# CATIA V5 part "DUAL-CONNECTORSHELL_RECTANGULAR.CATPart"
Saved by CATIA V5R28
Part number: DUAL-CONNECTOR_RECTANGULAR
Revision: ---
Publications: "Logical Termination.1", "Logical Pin.1", "CAVA", "Face_generated(CAV1)", "Axis_generated(CAV1)", "Face_generated(CAV1).1", "CAVB", "Face_generated(CAV2)", "Axis_generated(CAV2)", "Face_generated(CAV2).1", "CaCP", "Face_generated(CaCP1)", "Axis_generated(CaCP1)", "Face_generated(CaCP1).1", "BaCP", "BCP", "BCPRPoint_generated(BCP)", "BCPPlane_generated(BCP)", "Axis_generated(CAVA)", "Axis_generated(CAVB)", "Face_generated(BaCP)", "Axis_generated(BaCP)", "Face_generated(BaCP).1", "SCP", "Face_generated(SCP)", "Axis_generated(SCP)", "Face_generated(SCP).1"
Bounding box of the stored display mesh (mm): x 0 to 32.258, y -45.847 to 45.847, z -9.83 to 9.83
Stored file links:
  C:\Users\ajc8720\Documents\BOEING_WORK\0001-2CES\004-AP242\Boeing-Generic_Harness_R3\DUAL-CONNECTORSHELL_RECTANGULAR.CATPart
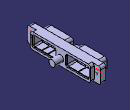
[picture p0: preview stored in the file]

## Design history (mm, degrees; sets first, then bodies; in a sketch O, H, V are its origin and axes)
Parameters
  PartNumber = "BACC65AA2AF"
  OverallLength = 21.59 mm
  OverallWidth = 91.694 mm
  OverallHeight = 19.6596 mm
  ShellBodyLength = 21.59 mm
  ShellFlangeThickness = 6.5024 mm
  ShellFlangeCornerRadius = 2.9972 mm
  ShellFlangeLocation = 10.668 mm
  ShellEngagingEndWidth = 30.9626 mm
  ShellEngagingEndHeight = 13.9446 mm
  ShellEngagingEndInsertCavityWidth = 27.051 mm
  ShellEngagingEndInsertCavityHeight = 11.2522 mm
  ShellEngagingEndOuterRadius = 3.1242 mm
  ShellEngagingEndInnerRadius = 1.7272 mm
  ShellRearInsertCavityWidth = 29.7942 mm
  ShellRearInsertCavityLength = 11.2014 mm
  ShellRearInsertCavityHeight = 14.1986 mm
  ShellInsertCavityRadius = 2.286 mm
  ShellInsertKeywayRadius = 3.5052 mm
  ShellInsertKeywayLength = 12.6492 mm
  ShellInsertKeywayDepth = 13.1826 mm
  ShellInsertKeywaySpacing = 7.62 mm
  BackInsertCavitySecondTransitionWidth = 27.1272 mm
  ShellCouplingPostVerticalLocation = 1.4986 mm
  CouplingPostOD = 7.9502 mm
  CouplingPostProtrusion = 10.668 mm
  ShellEngagingEndSpacing = 11.0744 mm
  CouplingPostID = 7.239 mm
  ShellEngagingEndInsertCavityDepth = 7.62 mm
  BackInsertCavitySecondTransitionRadius = 1.4986 mm
  BackInsertCavitySecondTransitionHeight = 12.0904 mm
  ShellRearWidth = 75.4888 mm
  ShellRearRadius = 2.9972 mm
  `Change of the Polarization Keyway` = "http://www.boeing.com/product_standards/tps2?part=\"BACC65AA2AF\"&suop=\"Change+of+the+Polarization+Keyway\""
  `Jackscrew Installation` = "http://www.boeing.com/product_standards/tps2?part=\"BACC65AA2AF\"&suop=\"Jackscrew+Installation\""
  `Jackscrew Removal` = "http://www.boeing.com/product_standards/tps2?part=\"BACC65AA2AF\"&suop=\"Jackscrew+Removal\""
  `Plug and Receptacle Connection` = "http://www.boeing.com/product_standards/tps2?part=\"BACC65AA2AF\"&suop=\"Plug+and+Receptacle+Connection\""
  P_Part_1 = "Loctite222"
  P_Name_1 = "Adhesive"
  P_Qty_1 = "As required"
TTRSSet1
f4a2d38f3ddc11d3a929006094b99c4b_11 "CATTPSSet"
Set1 "EGFOBody"
  Set2 "CaCPOBody1"
    Point1 "CaCPRPoint1": (10.668 {= ShellFlangeLocation}, 0, -1.4986 {= - BackInsertCavitySecondTransitionRadius})
    Plane1 "CaCPCPlane1": type OffsetPt, RefPlane yz-plane, RefPoint Point1
  Set3 "Construction Geometry"
    Plane2: type Offset, RefPlane yz-plane, Offset 21.59 {= ShellBodyLength}
    Sketch1 on Plane2, origin (21.59, 0, 0), H (0, 1, 0), V (0, 0, 1)
      line L1 (45.847, 6.8326) -> (45.847, -6.8326)
      line L2 (42.8498, -9.8298) -> (-42.8498, -9.8298)
      line L3 (-45.847, -6.8326) -> (-45.847, 6.8326)
      line L4 (-42.8498, 9.8298) -> (42.8498, 9.8298)
      point P1 (45.847, 9.8298)
      point P2 (45.847, -9.8298)
      point P3 (-45.847, 9.8298)
      arc A1 centre (42.8498, 6.8326) radius 2.9972 from (42.8498, 9.8298) to (45.847, 6.8326) cw
      arc A2 centre (42.8498, -6.8326) radius 2.9972 from (45.847, -6.8326) to (42.8498, -9.8298) cw
      arc A3 centre (-42.8498, -6.8326) radius 2.9972 from (-42.8498, -9.8298) to (-45.847, -6.8326) cw
      arc A4 centre (-42.8498, 6.8326) radius 2.9972 from (-45.847, 6.8326) to (-42.8498, 9.8298) cw
      distance P3 P1 = 91.694 {= OverallWidth}
      distance P1 P2 = 19.6596 {= OverallHeight}
      radius A1 = 2.9972 {= ShellFlangeCornerRadius}
      radius A2 = 2.9972 {= ShellFlangeCornerRadius}
      radius A3 = 2.9972 {= ShellFlangeCornerRadius}
      radius A4 = 2.9972 {= ShellFlangeCornerRadius}
      vertical: L1 V, L3 V
      horizontal: L2 H, L4 H
      equidistance: L1 L3 O, L2 L4 O
      coincidence: L4 P1, L1 P1, L1 P2, L2 P2, L3 P3, L4 P3
      tangency: A1 L4, A1 L1, A2 L1, A2 L2, A3 L2, A3 L3, A4 L3, A4 L4
    Plane3 "Ref Plane": type Offset, RefPlane yz-plane, Offset 0
    Plane4: type Offset, RefPlane Plane3, Offset 17.1704 {= ShellFlangeLocation + ShellFlangeThickness}
    Plane5: type Offset, RefPlane Plane3, Offset 10.668 {= ShellFlangeLocation}
    Plane6: type Offset, RefPlane Plane3, Offset 21.59 {= OverallLength}
    Plane7 "Keyway": type Offset, RefPlane Plane3, Offset 4.5212 {= (ShellFlangeLocation +ShellFlangeThickness )-ShellInsertKeywayLength}
    Plane8 "KeywayPlane": type Offset, RefPlane end face of Pad2, Offset 7.62 {= ShellEngagingEndInsertCavityDepth}
    Plane9: type Offset, RefPlane face of Pocket2 from Sketch4.L4, Offset 0, reversed
    Plane10: type Offset, RefPlane end face of Pocket1, Offset 0, reversed
  Set4 "CAVOBody1"
    Plane11 "CAVCPlane": type Offset, RefPlane Plane2, Offset 11.2014 {= ShellRearInsertCavityLength}, reversed
    Point2 "CAVRPoint1": type OnPlane, Support Plane11, H 21.0185 {= (ShellEngagingEndSpacing /2) + (ShellEngagingEndWidth /2)}, V 0, Direction (0, 1, 0)
  Set5 "CAVOBody2"
    Point3 "CAVRPoint2": type OnPlane, Support Plane11, H -21.0185 {= -((ShellEngagingEndSpacing /2) + (ShellEngagingEndWidth /2))}, V 0, Direction (0, 1, 0)
  Set6 "BaCPOBody"
    Point4 "BaCPRPoint": (21.59, 0, 0)
    Plane12 "BaCPPlane": type OffsetPt, RefPlane yz-plane, RefPoint Point4
    Line1 "BaCPCLine": type PtDir, RefPoint Point4, Direction zx-plane, Start 0, End -20
  Set7 "BCPOBody"
    Point5 "BCPRPoint": type OnPlane, Support Plane12, H 0, V 0, Direction (0, 1, 0)
    Plane13 "BCPPlane": type OffsetPt, RefPlane yz-plane, RefPoint Point5
  Set8 "SCPOBody"
    Point6 "SCPRPoint": (10.541, 0, 0)
    Plane14 "SCPCPlane": type OffsetPt, RefPlane end face of Pad1, RefPoint Point6
Body1 (main body)
  Pad1: profile Sketch1, direction (-1, 0, 0), up to Plane5
  Sketch2 on start face of Pad1, origin (21.59, 0, 0), H (0, 1, 0), V (0, 0, 1)
    line L1 (45.847, 6.8326) -> (45.847, -6.8326)
    line L2 (42.8498, -9.8298) -> (34.7472, -9.8298)
    line L3 (-45.847, -6.8326) -> (-45.847, 6.8326)
    line L4 (-42.8498, 9.8298) -> (-34.7472, 9.8298)
    point P1 (45.847, 9.8298)
    point P2 (45.847, -9.8298)
    point P3 (-45.847, 9.8298)
    arc A1 centre (42.8498, 6.8326) radius 2.9972 from (42.8498, 9.8298) to (45.847, 6.8326) cw
    arc A2 centre (42.8498, -6.8326) radius 2.9972 from (45.847, -6.8326) to (42.8498, -9.8298) cw
    arc A3 centre (-42.8498, -6.8326) radius 2.9972 from (-42.8498, -9.8298) to (-45.847, -6.8326) cw
    arc A4 centre (-42.8498, 6.8326) radius 2.9972 from (-45.847, 6.8326) to (-42.8498, 9.8298) cw
    line L5 (37.7444, 6.8326) -> (37.7444, -6.8326)
    line L6 (-37.7444, -6.8326) -> (-37.7444, 6.8326)
    point P16 (37.7444, 9.8298)
    point P17 (37.7444, -9.8298)
    point P18 (-37.7444, 9.8298)
    arc A5 centre (34.7472, 6.8326) radius 2.9972 from (34.7472, 9.8298) to (37.7444, 6.8326) cw
    arc A6 centre (34.7472, -6.8326) radius 2.9972 from (37.7444, -6.8326) to (34.7472, -9.8298) cw
    point P22 (34.7472, -9.8298)
    arc A7 centre (-34.7472, -6.8326) radius 2.9972 from (-34.7472, -9.8298) to (-37.7444, -6.8326) cw
    arc A8 centre (-34.7472, 6.8326) radius 2.9972 from (-37.7444, 6.8326) to (-34.7472, 9.8298) cw
    line L7 (-34.7472, -9.8298) -> (-42.8498, -9.8298)
    line L8 (34.7472, 9.8298) -> (42.8498, 9.8298)
    distance P3 P1 = 91.694 {= OverallWidth}
    distance P1 P2 = 19.6596 {= OverallHeight}
    radius A1 = 2.9972 {= ShellFlangeCornerRadius}
    radius A2 = 2.9972 {= ShellFlangeCornerRadius}
    radius A3 = 2.9972 {= ShellFlangeCornerRadius}
    radius A4 = 2.9972 {= ShellFlangeCornerRadius}
    distance P16 P17 = 19.6596 {= OverallHeight}
    radius A5 = 2.9972 {= ShellRearRadius}
    radius A6 = 2.9972 {= ShellRearRadius}
    radius A7 = 2.9972 {= ShellRearRadius}
    radius A8 = 2.9972 {= ShellRearRadius}
    distance L5 L6 = 75.4888 {= ShellRearWidth}
    vertical: L1 V, L3 V, L5 V, L6 V
    horizontal: L2 H, L4 H
    equidistance: L1 L3 O, L2 L4 O, L5 L6 O
    coincidence: L4 P1, L1 P1, L1 P2, L2 P2, L3 P3, L4 P3, L5 P16, L5 P17, L6 P18, L2 L7, P22 L2, P22 A6, P22 L7, L4 L8
    tangency: A1 L4, A1 L1, A2 L1, A2 L2, A3 L2, A3 L3, A4 L3, A4 L4, A5 L5, A6 L5, A7 L6, A8 L6, A8 L4, A7 L7, A6 L2, A5 L8
    symmetry: L5 L6 V
  Pocket1: profile Sketch2, direction (-1, 0, 0), length 4.4196 {= ShellBodyLength -ShellFlangeThickness -ShellFlangeLocation}
  Sketch3 on end face of Pad1, origin (10.668, 0, 0), H (0, -1, 0), V (0, 0, 1)
    point P1 (21.0185, 0)
    line L1 (36.4998, 3.8481) -> (36.4998, -3.8481)
    line L2 (33.3756, -6.9723) -> (8.6614, -6.9723)
    line L3 (5.5372, -3.8481) -> (5.5372, 3.8481)
    line L4 (8.6614, 6.9723) -> (33.3756, 6.9723)
    point P2 (36.4998, 6.9723)
    point P3 (36.4998, -6.9723)
    point P4 (5.5372, 6.9723)
    point P5 (-21.0185, 0)
    line L5 (-5.5372, 3.8481) -> (-5.5372, -3.8481)
    line L6 (-8.6614, -6.9723) -> (-33.3756, -6.9723)
    line L7 (-36.4998, -3.8481) -> (-36.4998, 3.8481)
    line L8 (-33.3756, 6.9723) -> (-8.6614, 6.9723)
    point P6 (-5.5372, 6.9723)
    point P7 (-36.4998, 6.9723)
    arc A1 centre (33.3756, 3.8481) radius 3.1242 from (33.3756, 6.9723) to (36.4998, 3.8481) cw
    arc A2 centre (33.3756, -3.8481) radius 3.1242 from (36.4998, -3.8481) to (33.3756, -6.9723) cw
    arc A3 centre (8.6614, -3.8481) radius 3.1242 from (8.6614, -6.9723) to (5.5372, -3.8481) cw
    arc A4 centre (8.6614, 3.8481) radius 3.1242 from (5.5372, 3.8481) to (8.6614, 6.9723) cw
    arc A5 centre (-8.6614, 3.8481) radius 3.1242 from (-5.5372, 3.8481) to (-8.6614, 6.9723) ccw
    arc A6 centre (-8.6614, -3.8481) radius 3.1242 from (-5.5372, -3.8481) to (-8.6614, -6.9723) cw
    arc A7 centre (-33.3756, -3.8481) radius 3.1242 from (-33.3756, -6.9723) to (-36.4998, -3.8481) cw
    arc A8 centre (-33.3756, 3.8481) radius 3.1242 from (-36.4998, 3.8481) to (-33.3756, 6.9723) cw
    distance P1 V = 21.0185 {= (ShellEngagingEndSpacing/2)+(ShellEngagingEndWidth /2)}
    distance P4 P2 = 30.9626 {= ShellEngagingEndWidth}
    distance P2 P3 = 13.9446 {= ShellEngagingEndHeight}
    radius A1 = 3.1242 {= ShellEngagingEndOuterRadius}
    radius A2 = 3.1242 {= ShellEngagingEndOuterRadius}
    radius A3 = 3.1242 {= ShellEngagingEndOuterRadius}
    radius A4 = 3.1242 {= ShellEngagingEndOuterRadius}
    distance P7 P6 = 30.9626 {= ShellEngagingEndWidth}
    radius A5 = 3.1242 {= ShellEngagingEndOuterRadius}
    radius A6 = 3.1242 {= ShellEngagingEndOuterRadius}
    radius A7 = 3.1242 {= ShellEngagingEndOuterRadius}
    radius A8 = 3.1242 {= ShellEngagingEndOuterRadius}
    coincidence: P1 H, P5 H, L8 L4, L4 P2, L1 P2, L1 P3, L2 P3, L3 P4, L4 P4, L5 P6, L8 P6, L7 P7, L8 P7
    vertical: L1 V, L3 V, L5 V, L7 V
    horizontal: L2 H, L4 H, L6 H, L8 H
    equidistance: L1 L3 P1, L2 L4 P1, L5 L7 P5, L6 L8 P5
    symmetry: P1 P5 V
    tangency: A1 L4, A1 L1, A2 L1, A2 L2, A3 L2, A3 L3, A4 L3, A4 L4, A5 L5, A5 L8, A6 L5, A6 L6, A7 L6, A7 L7, A8 L7, A8 L8
  Pad2: profile Sketch3, direction (-1, 0, 0), length 10.668 {= ShellFlangeLocation}
  Sketch4 on start face of Pad1, origin (21.59, 0, 0), H (0, 1, 0), V (0, 0, 1)
    point P1 (21.0185, 0)
    line L1 (35.9156, 4.8133) -> (35.9156, -4.8133)
    line L2 (33.6296, -7.0993) -> (8.4074, -7.0993)
    line L3 (6.1214, -4.8133) -> (6.1214, 4.8133)
    line L4 (8.4074, 7.0993) -> (33.6296, 7.0993)
    point P2 (35.9156, 7.0993)
    point P3 (35.9156, -7.0993)
    point P4 (6.1214, 7.0993)
    point P5 (-21.0185, 0)
    line L5 (-35.9156, 4.8133) -> (-35.9156, -4.8133)
    line L6 (-33.6296, -7.0993) -> (-8.4074, -7.0993)
    line L7 (-6.1214, -4.8133) -> (-6.1214, 4.8133)
    line L8 (-8.4074, 7.0993) -> (-33.6296, 7.0993)
    point P6 (-35.9156, 7.0993)
    point P7 (-6.1214, 7.0993)
    reference intersected line E2 through (0, 0) direction (0, 1) from zx-plane
    arc A1 centre (33.6296, 4.8133) radius 2.286 from (33.6296, 7.0993) to (35.9156, 4.8133) cw
    arc A2 centre (33.6296, -4.8133) radius 2.286 from (35.9156, -4.8133) to (33.6296, -7.0993) cw
    arc A3 centre (8.4074, -4.8133) radius 2.286 from (8.4074, -7.0993) to (6.1214, -4.8133) cw
    arc A4 centre (8.4074, 4.8133) radius 2.286 from (6.1214, 4.8133) to (8.4074, 7.0993) cw
    arc A5 centre (-8.4074, 4.8133) radius 2.286 from (-6.1214, 4.8133) to (-8.4074, 7.0993) ccw
    arc A6 centre (-8.4074, -4.8133) radius 2.286 from (-6.1214, -4.8133) to (-8.4074, -7.0993) cw
    arc A7 centre (-33.6296, -4.8133) radius 2.286 from (-33.6296, -7.0993) to (-35.9156, -4.8133) cw
    arc A8 centre (-33.6296, 4.8133) radius 2.286 from (-35.9156, 4.8133) to (-33.6296, 7.0993) cw
    distance V P1 = 21.0185 {= (ShellEngagingEndSpacing /2)+(ShellEngagingEndWidth /2)}
    distance P4 P2 = 29.7942 {= ShellRearInsertCavityWidth}
    distance P2 P3 = 14.1986 {= ShellRearInsertCavityHeight}
    radius A1 = 2.286 {= ShellInsertCavityRadius}
    radius A2 = 2.286 {= ShellInsertCavityRadius}
    radius A3 = 2.286 {= ShellInsertCavityRadius}
    radius A4 = 2.286 {= ShellInsertCavityRadius}
    distance P7 P6 = 29.7942 {= ShellRearInsertCavityWidth}
    radius A5 = 2.286 {= ShellInsertCavityRadius}
    radius A6 = 2.286 {= ShellInsertCavityRadius}
    radius A7 = 2.286 {= ShellInsertCavityRadius}
    radius A8 = 2.286 {= ShellInsertCavityRadius}
    coincidence: P1 H, P5 H, L4 L8, L6 L2, L4 P2, L1 P2, L1 P3, L2 P3, L3 P4, L4 P4, L7 P7, L8 P7, L5 P6, L8 P6
    vertical: L1 V, L3 V, L5 V, L7 V
    horizontal: L2 H, L4 H, L6 H, L8 H
    equidistance: L1 L3 P1, L2 L4 P1, L5 L7 P5, L6 L8 P5
    symmetry: P5 P1 E2
    tangency: A1 L4, A1 L1, A2 L1, A2 L2, A3 L2, A3 L3, A4 L3, A4 L4, A5 L7, A5 L8, A6 L7, A6 L6, A7 L6, A7 L5, A8 L5, A8 L8
  Pocket2: profile Sketch4, direction (-1, 0, 0), length 1.3208 {= ShellBodyLength -ShellEngagingEndInsertCavityDepth -ShellInsertKeywayLength}
  Sketch5 on end face of Pocket2, origin (20.2692, 0, 0), H (0, 1, 0), V (0, 0, 1)
    point P1 (21.0185, 0)
    line L1 (34.5821, 4.5466) -> (34.5821, -4.5466)
    line L2 (33.0835, -6.0452) -> (8.9535, -6.0452)
    line L3 (7.4549, -4.5466) -> (7.4549, 4.5466)
    line L4 (8.9535, 6.0452) -> (33.0835, 6.0452)
    point P2 (34.5821, 6.0452)
    point P3 (34.5821, -6.0452)
    point P4 (7.4549, 6.0452)
    point P5 (-21.0185, 0)
    line L5 (-7.4549, 4.5466) -> (-7.4549, -4.5466)
    line L6 (-8.9535, -6.0452) -> (-33.0835, -6.0452)
    line L7 (-34.5821, -4.5466) -> (-34.5821, 4.5466)
    line L8 (-33.0835, 6.0452) -> (-8.9535, 6.0452)
    point P6 (-7.4549, 6.0452)
    point P7 (-34.5821, 6.0452)
    reference intersected line E1 through (0, 0) direction (0, 1) from zx-plane
    arc A1 centre (33.0835, 4.5466) radius 1.4986 from (34.5821, 4.5466) to (33.0835, 6.0452) ccw
    arc A2 centre (33.0835, -4.5466) radius 1.4986 from (34.5821, -4.5466) to (33.0835, -6.0452) cw
    arc A3 centre (8.9535, -4.5466) radius 1.4986 from (8.9535, -6.0452) to (7.4549, -4.5466) cw
    arc A4 centre (8.9535, 4.5466) radius 1.4986 from (7.4549, 4.5466) to (8.9535, 6.0452) cw
    arc A5 centre (-8.9535, 4.5466) radius 1.4986 from (-8.9535, 6.0452) to (-7.4549, 4.5466) cw
    arc A6 centre (-8.9535, -4.5466) radius 1.4986 from (-7.4549, -4.5466) to (-8.9535, -6.0452) cw
    arc A7 centre (-33.0835, -4.5466) radius 1.4986 from (-33.0835, -6.0452) to (-34.5821, -4.5466) cw
    arc A8 centre (-33.0835, 4.5466) radius 1.4986 from (-34.5821, 4.5466) to (-33.0835, 6.0452) cw
    distance P1 V = 21.0185 {= (ShellEngagingEndSpacing /2)+(ShellEngagingEndWidth /2)}
    distance P2 P3 = 12.0904 {= BackInsertCavitySecondTransitionHeight}
    distance P4 P2 = 27.1272 {= BackInsertCavitySecondTransitionWidth}
    radius A1 = 1.4986 {= BackInsertCavitySecondTransitionRadius}
    radius A2 = 1.4986 {= BackInsertCavitySecondTransitionRadius}
    radius A3 = 1.4986 {= BackInsertCavitySecondTransitionRadius}
    radius A4 = 1.4986 {= BackInsertCavitySecondTransitionRadius}
    distance P7 P6 = 27.1272 {= BackInsertCavitySecondTransitionWidth}
    radius A5 = 1.4986 {= BackInsertCavitySecondTransitionRadius}
    radius A6 = 1.4986 {= BackInsertCavitySecondTransitionRadius}
    radius A7 = 1.4986 {= BackInsertCavitySecondTransitionRadius}
    radius A8 = 1.4986 {= BackInsertCavitySecondTransitionRadius}
    coincidence: P1 H, P5 H, P6 L4, L4 L8, L6 L2, L1 P2, L4 P2, L1 P3, L2 P3, L3 P4, L4 P4, L8 P6, L5 P6, L7 P7, L8 P7
    vertical: L1 V, L3 V, L5 V, L7 V
    horizontal: L2 H, L4 H, L6 H, L8 H
    equidistance: L1 L3 P1, L2 L4 P1, L5 L7 P5, L6 L8 P5
    symmetry: P1 P5 E1
    tangency: A1 L1, A1 L4, A2 L1, A2 L2, A3 L2, A3 L3, A4 L3, A4 L4, A5 L8, A5 L5, A6 L5, A6 L6, A7 L6, A7 L7, A8 L7, A8 L8
  Pocket3: profile Sketch5, direction (-1, 0, 0), length 9.8806 {= ShellRearInsertCavityLength -(ShellBodyLength -ShellEngagingEndInsertCavityDepth -ShellInsertKeywayLength )}
  Sketch6 on end face of Pad2, origin (0, 0, 0), H (0, 1, 0), V (0, 0, 1)
    point P1 (21.0185, 0)
    line L1 (34.544, 3.8989) -> (34.544, -3.8989)
    line L2 (32.8168, -5.6261) -> (9.2202, -5.6261)
    line L3 (7.493, -3.8989) -> (7.493, 3.8989)
    line L4 (9.2202, 5.6261) -> (32.8168, 5.6261)
    point P2 (34.544, 5.6261)
    point P3 (34.544, -5.6261)
    point P4 (7.493, 5.6261)
    point P5 (-21.0185, 0)
    line L5 (-7.493, 3.8989) -> (-7.493, -3.8989)
    line L6 (-9.2202, -5.6261) -> (-32.8168, -5.6261)
    line L7 (-34.544, -3.8989) -> (-34.544, 3.8989)
    line L8 (-32.8168, 5.6261) -> (-9.2202, 5.6261)
    point P6 (-7.493, 5.6261)
    point P7 (-34.544, 5.6261)
    reference intersected line E1 through (0, 0) direction (0, 1) from zx-plane
    reference intersected line E2 through (0, 0) direction (0, 1) from zx-plane
    arc A1 centre (32.8168, 3.8989) radius 1.7272 from (32.8168, 5.6261) to (34.544, 3.8989) cw
    arc A2 centre (32.8168, -3.8989) radius 1.7272 from (34.544, -3.8989) to (32.8168, -5.6261) cw
    arc A3 centre (9.2202, -3.8989) radius 1.7272 from (9.2202, -5.6261) to (7.493, -3.8989) cw
    arc A4 centre (9.2202, 3.8989) radius 1.7272 from (7.493, 3.8989) to (9.2202, 5.6261) cw
    arc A5 centre (-9.2202, 3.8989) radius 1.7272 from (-9.2202, 5.6261) to (-7.493, 3.8989) cw
    arc A6 centre (-9.2202, -3.8989) radius 1.7272 from (-7.493, -3.8989) to (-9.2202, -5.6261) cw
    arc A7 centre (-32.8168, 3.8989) radius 1.7272 from (-34.544, 3.8989) to (-32.8168, 5.6261) cw
    arc A8 centre (-32.8168, -3.8989) radius 1.7272 from (-32.8168, -5.6261) to (-34.544, -3.8989) cw
    distance E2 P1 = 21.0185 {= (ShellEngagingEndSpacing /2)+(ShellEngagingEndWidth /2)}
    distance P4 P2 = 27.051 {= ShellEngagingEndInsertCavityWidth}
    distance P2 P3 = 11.2522 {= ShellEngagingEndInsertCavityHeight}
    radius A2 = 1.7272 {= ShellEngagingEndInnerRadius}
    radius A3 = 1.7272 {= ShellEngagingEndInnerRadius}
    radius A4 = 1.7272 {= ShellEngagingEndInnerRadius}
    distance P7 P6 = 27.051 {= ShellEngagingEndInsertCavityWidth}
    radius A5 = 1.7272 {= ShellEngagingEndInnerRadius}
    radius A6 = 1.7272 {= ShellEngagingEndInnerRadius}
    radius A7 = 1.7272 {= ShellEngagingEndInnerRadius}
    radius A8 = 1.7272 {= ShellEngagingEndInnerRadius}
    radius A1 = 1.7272 {= ShellEngagingEndInnerRadius}
    vertical: L1 V, L3 V, L5 V, L7 V
    horizontal: L2 H, L4 H, L6 H, L8 H
    equidistance: L1 L3 P1, L2 L4 P1, L5 L7 P5, L6 L8 P5
    coincidence: P5 H, P6 L4, L2 L6, L4 L8, L4 P2, L1 P2, L1 P3, L2 P3, L3 P4, L4 P4, L8 P6, L5 P6, L7 P7, L8 P7
    symmetry: P5 P1 E1
    tangency: A1 L4, A1 L1, A2 L1, A2 L2, A3 L2, A3 L3, A4 L3, A4 L4, A5 L8, A5 L5, A6 L5, A6 L6, A7 L7, A7 L8, A8 L6, A8 L7
  Pocket4: profile Sketch6, direction (1, 0, 0), through (limit type 6)
  Sketch7 on start face of Pad1, origin (21.59, 0, 0), H (0, 1, 0), V (0, 0, 1)
    circle A1 centre (0, -1.4986) radius 3.9751
    point P1 (0, -1.4986)
    reference intersected line E1 through (0, 0) direction (-1, 0) from xy-plane
    radius A1 = 3.9751 {= CouplingPostOD /2}
    distance E1 P1 = 1.4986 {= ShellCouplingPostVerticalLocation}
    coincidence: P1 V
  Pad3: profile Sketch7, direction (1, 0, 0), length 10.668 {= (OverallLength -ShellBodyLength )+CouplingPostProtrusion}
  Sketch8 on end face of Pad1, origin (10.668, 0, 0), H (0, -1, 0), V (0, 0, 1)
    circle A1 centre (0, -1.4986) radius 3.9751
    point P1 (0, -1.4986)
    circle A2 centre (0, -1.4986) radius 3.6195
    point P2 (0, -1.4986)
    radius A1 = 3.9751 {= CouplingPostOD /2}
    distance H P1 = 1.4986 {= ShellCouplingPostVerticalLocation}
    radius A2 = 3.6195 {= CouplingPostID /2}
    coincidence: P1 V, P2 V, P2 P1
  Pad4: profile Sketch8, direction (-1, 0, 0), length 10.668 {= ShellFlangeLocation}
  Sketch9 on Plane8, origin (7.62, 0, 0), H (0, 1, 0), V (0, 0, 1)
    circle A1 centre (-24.8285, -2.5781) radius 3.5052
    point P1 (-24.8285, -2.5781)
    circle A2 centre (-17.2085, -2.5781) radius 3.5052
    point P2 (-17.2085, -2.5781)
    circle A3 centre (21.0185, -2.5781) radius 3.5052
    point P3 (21.0185, -2.5781)
    reference intersected line E1 through (0, 7.0993) direction (-1, 0) from Plane9
    reference intersected line E2 through (0, 7.0993) direction (-1, 0) from Plane9
    reference intersected line E3 through (0, 7.0993) direction (-1, 0) from Plane9
    radius A3 = 3.5052 {= ShellInsertKeywayRadius}
    radius A2 = 3.5052 {= ShellInsertKeywayRadius}
    radius A1 = 3.5052 {= ShellInsertKeywayRadius}
    distance A1 E1 = 13.1826 {= ShellInsertKeywayDepth}
    distance A2 E2 = 13.1826 {= ShellInsertKeywayDepth}
    distance A3 E3 = 13.1826 {= ShellInsertKeywayDepth}
    distance P2 P1 H = 7.62 {= ShellInsertKeywaySpacing}
    distance P2 V = 17.2085 {= (ShellEngagingEndSpacing /2)+(ShellEngagingEndWidth /2) - (ShellInsertKeywaySpacing /2)}
    distance V P3 = 21.0185 {= (ShellEngagingEndSpacing /2)+(ShellEngagingEndWidth /2)}
  Pocket5: profile Sketch9, direction (1, 0, 0), length 12.6492 {= ShellInsertKeywayLength}
Body2 "Male Cherbourg - SCP"
  Sketch10 "Copy of Sketch" on Plane14, origin (10.541, 0, 0), H (0, 1, 0), V (0, 0, 1)
    line L1 (-0.672, 0.762) -> (0.672, 0.762)
    point P1 (-0.672, 0.762)
    point P2 (0.672, 0.762)
    arc A1 centre (0, 0) radius 1.016 from (-1.016, 0) to (1.016, 0) ccw
    point P3 (0, 0)
    point P4 (-1.016, 0)
    point P5 (1.016, 0)
    reference projected point E1 (0, 0) from Point6
    arc A2 centre (0, 0) radius 1.016 from (1.016, 0) to (0.672, 0.762) ccw
    point P6 (0, 0)
    point P7 (1.016, 0)
    point P8 (0.672, 0.762)
    arc A3 centre (0, 0) radius 1.016 from (-0.672, 0.762) to (-1.016, 0) ccw
    point P9 (0, 0)
    point P10 (-0.672, 0.762)
    point P11 (-1.016, 0)
    reference projected point E2 (0, 0) from Point6
    reference projected point E3 (0, 0) from Point6
    length L1 = 1.344
    radius A1 = 1.016
    radius A3 = 1.016
    radius A2 = 1.016
    distance L1 P5 = 0.762
    distance P4 L1 = 0.762
    distance P7 L1 = 0.762
    distance P11 L1 = 0.762
    coincidence: P3 E1, P6 E2, P9 E3, P8 P2, P10 P1
    horizontal: L1 H
  Pad5: profile Sketch10, direction (1, 0, 0), length 0.508, opposite side up to Plane14
Body3 "Female Cherbourg - BaCP"
  Sketch11 "Copy of Sketch.1" on Plane12, origin (21.59, 0, 0), H (0, 1, 0), V (0, 0, 1)
    circle A1 centre (0, 0) radius 1.27
    point P1 (0, 0)
    reference projected point E1 (0, 0) from Point4
    radius A1 = 1.27
    coincidence: P1 E1
  Pad6: profile Sketch11, direction (1, 0, 0), length 0.254, opposite side length 0.254
  Sketch12 "Copy of Sketch.2" on Plane12, origin (21.59, 0, 0), H (0, -1, 0), V (0, 0, -1)
    line L1 (-0.672, 0.762) -> (0.672, 0.762)
    point P1 (-0.672, 0.762)
    point P2 (0.672, 0.762)
    arc A1 centre (0, 0) radius 1.016 from (-1.016, 0) to (1.016, 0) ccw
    point P3 (0, 0)
    point P4 (-1.016, 0)
    point P5 (1.016, 0)
    reference projected point E1 (0, 0) from Point4
    arc A2 centre (0, 0) radius 1.016 from (1.016, 0) to (0.672, 0.762) ccw
    point P6 (0, 0)
    point P7 (1.016, 0)
    point P8 (0.672, 0.762)
    arc A3 centre (0, 0) radius 1.016 from (-0.672, 0.762) to (-1.016, 0) ccw
    point P9 (0, 0)
    point P10 (-0.672, 0.762)
    point P11 (-1.016, 0)
    reference projected point E2 (0, 0) from Point4
    reference projected point E3 (0, 0) from Point4
    length L1 = 1.344
    radius A1 = 1.016
    radius A3 = 1.016
    radius A2 = 1.016
    distance L1 P5 = 0.762
    distance P4 L1 = 0.762
    distance P7 L1 = 0.762
    distance P11 L1 = 0.762
    coincidence: P3 E1, P6 E2, P9 E3, P8 P2, P10 P1
    horizontal: L1 H
  Pocket6: profile Sketch12, direction (1, 0, 0), through (limit type 6)
Body4 "Female-Cherbourg-CAV-A"
  Sketch13 on Plane11, origin (10.3886, 21.0185, 0), H (0, 1, 0), V (0, 0, 1)
    arc A1 centre (0, 0) radius 1.016 from (-0.672, 0.762) to (0.672, 0.762) ccw
    line L1 (-0.672, 0.762) -> (0.672, 0.762)
    distance L1 H = 0.762
    radius A1 = 1.016
  Sketch14 on Plane11, origin (10.3886, 21.0185, 0), H (0, 1, 0), V (0, 0, 1)
    circle A1 centre (0, 0) radius 1.27
    radius A1 = 1.27
  Pad7: profile Sketch14, direction (1, 0, 0), length 0.254, opposite side length 0.254
  Pocket7: profile Sketch13, direction (1, 0, 0), through (limit type 6)
Body5 "Female-Cherbourg-CAV-B"
  Sketch15 on Plane11, origin (10.3886, -21.0185, 0), H (0, 1, 0), V (0, 0, 1)
    arc A1 centre (0, 0) radius 1.016 from (-0.672, 0.762) to (0.672, 0.762) ccw
    line L1 (-0.672, 0.762) -> (0.672, 0.762)
    distance L1 H = 0.762
    radius A1 = 1.016
  Sketch16 on Plane11, origin (10.3886, -21.0185, 0), H (0, 1, 0), V (0, 0, 1)
    circle A1 centre (0, 0) radius 1.27
    radius A1 = 1.27
  Pad8: profile Sketch16, direction (1, 0, 0), length 0.254, opposite side length 0.254
  Pocket8: profile Sketch15, direction (1, 0, 0), through (limit type 6)
Body6 "Male Cherbourg - CaCP"
  Sketch17 "Sketch" on Plane1, origin (10.668, 0, -1.4986), H (0, 1, 0), V (0, 0, 1)
    line L1 (-0.672, 0.762) -> (0.672, 0.762)
    point P1 (-0.672, 0.762)
    point P2 (0.672, 0.762)
    arc A1 centre (0, 0) radius 1.016 from (-1.016, 0) to (1.016, 0) ccw
    point P3 (0, 0)
    point P4 (-1.016, 0)
    point P5 (1.016, 0)
    reference projected point E1 (0, 0) from Point1
    arc A2 centre (0, 0) radius 1.016 from (1.016, 0) to (0.672, 0.762) ccw
    point P6 (0, 0)
    point P7 (1.016, 0)
    point P8 (0.672, 0.762)
    arc A3 centre (0, 0) radius 1.016 from (-0.672, 0.762) to (-1.016, 0) ccw
    point P9 (0, 0)
    point P10 (-0.672, 0.762)
    point P11 (-1.016, 0)
    reference projected point E2 (0, 0) from Point1
    reference projected point E3 (0, 0) from Point1
    length L1 = 1.344
    radius A1 = 1.016
    radius A3 = 1.016
    radius A2 = 1.016
    distance L1 P5 = 0.762
    distance P4 L1 = 0.762
    distance P7 L1 = 0.762
    distance P11 L1 = 0.762
    coincidence: P3 E1, P6 E2, P9 E3, P8 P2, P10 P1
    horizontal: L1 H
  Pad9: profile Sketch17, direction (1, 0, 0), length 0.508, opposite side up to Plane1
Relations
  Pad1.FirstLimit.Length = ShellFlangeThickness
  Pocket4.FirstLimit.Depth = ShellEngagingEndInsertCavityDepth (deactivated)
  P_Part = P_Part_1
  P_Name = P_Name_1
  P_Qty = P_Qty_1
  URI_LINK = `Change of the Polarization Keyway`
  URI_LINK = `Jackscrew Installation`
  URI_LINK = `Jackscrew Removal`
  URI_LINK = `Plug and Receptacle Connection`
